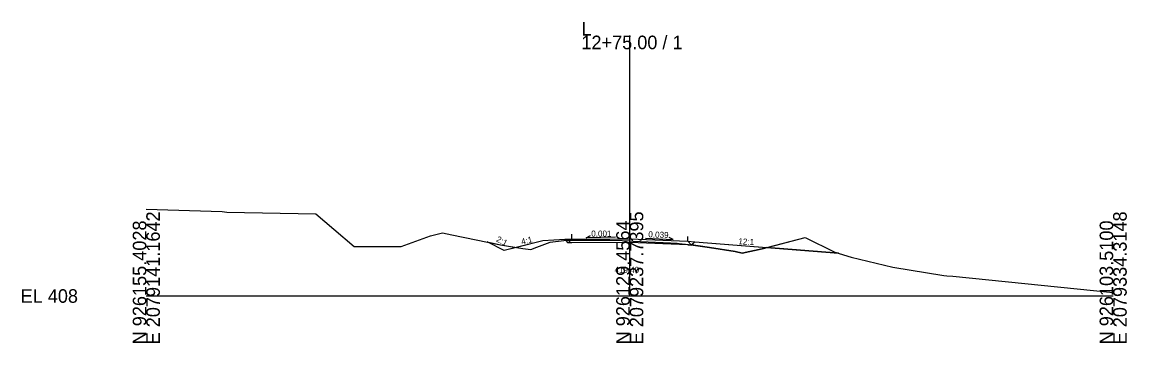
# Model space of a CAD drawing. Extents: x -26 to 10503, y -10 to 9546.
# Drawn here: x -25.7 to 202.8, y 5490.3 to 5556.6 of the extents above; entities that cross this region are included whole.
import ezdxf

# ---------------------------------------------------------------- set-up
doc = ezdxf.new("R2010")
doc.units = 0
for name, color, linetype in [('Default', 7, 'Continuous'), ('Exist XS Center Line Elevation Label', 7, 'Continuous'), ('Exist XS Ground Line', 7, 'Continuous'), ('Old_Level_63', 7, 'Continuous'), ('Prop XS Ditch Slope Text', 7, 'Continuous'), ('Prop XS Dump Level', 7, 'Continuous'), ('Prop XS EOT Tick Mark', 7, 'Continuous'), ('Prop XS Finish Grade', 7, 'Continuous'), ('Prop XS Finish Grade Earthwork', 7, 'Continuous'), ('Prop XS Finish Grade Pavement', 7, 'Continuous'), ('Prop XS Pvmt Edge Slope', 7, 'Continuous'), ('Prop XS SE Text', 7, 'Continuous'), ('Prop XS Side Slope Text', 7, 'Continuous'), ('Prop XS Subgrade Earthwork', 7, 'Continuous')]:
    doc.layers.add(name, color=color, linetype=linetype)

msp = doc.modelspace()

# ---------------------------------------------------------------- linework, layer by layer
at = {"layer": 'Default'}
for points in [[(74, 5509.4), (70.48, 5511.16), (73.27, 5510.6), (76.56, 5510.05)], [(86.58, 5511.68), (82, 5511.4), (76.56, 5510.05), (77.9, 5509.82), (79.52, 5509.6), (80.76, 5510.06), (83.55, 5511.13), (86.34, 5511.47), (86.75, 5511.52)], [(88, 5511.02), (87.25, 5511.02), (86.75, 5511.52), (87.14, 5511.56), (95.88, 5511.53), (98.43, 5511.5), (100, 5511.4), (100.73, 5511.36), (108.4, 5510.98), (109.84, 5510.89), (110.25, 5510.86), (112.18, 5510.63), (112.79, 5510.55), (112.78, 5510.53), (112, 5510.56), (100, 5511.03)], [(113.45, 5511.2), (128.39, 5510), (127.38, 5509.74), (123.27, 5508.84), (121.81, 5509.18), (116.49, 5510.05), (112.79, 5510.55)], [(128.39, 5510), (136.32, 5512.06), (142.4, 5509.07), (143.2, 5508.82)]]:
    msp.add_lwpolyline(points, close=True, dxfattribs=at)
at = {"layer": 'Exist XS Ground Line'}
for p, q in [((0, 5517.94), (15.72, 5517.49)), ((15.72, 5517.49), (16.67, 5517.35)), ((16.67, 5517.35), (35.07, 5516.99)), ((35.07, 5516.99), (38.81, 5513.81)), ((38.81, 5513.81), (43.02, 5510.24)), ((52.71, 5510.23), (58.78, 5512.41)), ((58.78, 5512.41), (61.27, 5513.07)), ((61.27, 5513.07), (63.19, 5512.64)), ((63.19, 5512.64), (73.27, 5510.6)), ((43.02, 5510.24), (46.28, 5510.26)), ((46.28, 5510.26), (52.71, 5510.23)), ((73.27, 5510.6), (77.9, 5509.82)), ((79.52, 5509.6), (80.76, 5510.06)), ((80.76, 5510.06), (83.55, 5511.13)), ((83.55, 5511.13), (86.34, 5511.47)), ((86.34, 5511.47), (87.14, 5511.56)), ((87.14, 5511.56), (95.88, 5511.53)), ((95.88, 5511.53), (98.43, 5511.5)), ((98.43, 5511.5), (100, 5511.4)), ((100, 5511.4), (100.73, 5511.36)), ((100.73, 5511.36), (108.4, 5510.98)), ((108.4, 5510.98), (109.84, 5510.89)), ((109.84, 5510.89), (110.25, 5510.86)), ((110.25, 5510.86), (112.18, 5510.63)), ((112.18, 5510.63), (116.49, 5510.05)), ((116.49, 5510.05), (121.81, 5509.18)), ((127.38, 5509.74), (136.32, 5512.06)), ((136.32, 5512.06), (142.4, 5509.07)), ((77.9, 5509.82), (79.52, 5509.6)), ((121.81, 5509.18), (123.27, 5508.84)), ((123.27, 5508.84), (127.38, 5509.74)), ((142.4, 5509.07), (145.78, 5508.01)), ((145.78, 5508.01), (154.42, 5505.95)), ((154.42, 5505.95), (164.99, 5504.22)), ((164.99, 5504.22), (165.59, 5504.18)), ((165.59, 5504.18), (166.84, 5504.12)), ((166.84, 5504.12), (200, 5500.69))]:
    msp.add_line(p, q, dxfattribs=at)
at = {"layer": 'Old_Level_63'}
for p, q in [((100, 5500), (100, 5553.81)), ((0, 5500), (100, 5500)), ((100, 5500), (200, 5500))]:
    msp.add_line(p, q, dxfattribs=at)
at = {"layer": 'Prop XS EOT Tick Mark'}
for p, q in [((88, 5511.77), (88, 5512.77)), ((112, 5511.31), (112, 5512.31))]:
    msp.add_line(p, q, dxfattribs=at)
at = {"layer": 'Prop XS Finish Grade'}
for p, q in [((88, 5511.77), (86.58, 5511.68)), ((112, 5511.31), (113.45, 5511.2))]:
    msp.add_line(p, q, dxfattribs=at)
at = {"layer": 'Prop XS Finish Grade Earthwork'}
for p, q in [((74, 5509.4), (70.48, 5511.16)), ((82, 5511.4), (74, 5509.4)), ((86.58, 5511.68), (82, 5511.4)), ((113.45, 5511.2), (143.2, 5508.82))]:
    msp.add_line(p, q, dxfattribs=at)
at = {"layer": 'Prop XS Finish Grade Pavement'}
for p, q in [((88, 5511.77), (100, 5511.78)), ((100, 5511.78), (112, 5511.31))]:
    msp.add_line(p, q, dxfattribs=at)
at = {"layer": 'Prop XS Pvmt Edge Slope'}
for p, q in [((88, 5511.77), (87.25, 5511.02)), ((112, 5511.31), (112.78, 5510.53))]:
    msp.add_line(p, q, dxfattribs=at)
at = {"layer": 'Prop XS SE Text'}
for points in [[(97.03, 5512.15), (91.01, 5512.04), (91.87, 5512.5)], [(103.23, 5511.92), (108.98, 5511.65), (108.13, 5512.11)]]:
    msp.add_lwpolyline(points, dxfattribs=at)
at = {"layer": 'Prop XS Subgrade Earthwork'}
for p, q in [((87.25, 5511.02), (86.58, 5511.68)), ((88, 5511.02), (87.25, 5511.02)), ((100, 5511.03), (88, 5511.02)), ((112, 5510.56), (100, 5511.03)), ((112, 5510.56), (112.78, 5510.53)), ((112.78, 5510.53), (113.45, 5511.2))]:
    msp.add_line(p, q, dxfattribs=at)

# ---------------------------------------------------------------- texts
at = {"layer": 'Exist XS Center Line Elevation Label'}
msp.add_text('419.40', height=1.25, rotation=360, dxfattribs=at).set_placement((96.84, 5504.78))
at = {"layer": 'Old_Level_63'}
for s, p in [('L', (90, 5553.81)), ('12+75.00 / 1', (90, 5551.01)), ('EL 408', (-26, 5498.6))]:
    msp.add_text(s, height=2.8, dxfattribs=at).set_placement(p)
for s, p in [('E 2079141.1642', (2.8, 5490)), ('E 2079237.7395', (102.8, 5490)), ('E 2079334.3148', (202.8, 5490)), ('N 926155.4028', (0, 5490)), ('N 926129.4564', (100, 5490)), ('N 926103.5100', (200, 5490))]:
    msp.add_text(s, height=2.8, rotation=90, dxfattribs=at).set_placement(p)
at = {"layer": 'Prop XS Ditch Slope Text'}
for s, rotation, p in [('4:1', 14.0362, (77.71, 5510.57)), ('12:1', 356.5563, (122.45, 5510.7))]:
    msp.add_text(s, height=1.25, rotation=rotation, dxfattribs=at).set_placement(p)
at = {"layer": 'Prop XS Dump Level'}
msp.add_text('Case1', height=0.04, dxfattribs=at).set_placement((120, 5510.63))
at = {"layer": 'Prop XS SE Text'}
for s, rotation, p in [('0.001', 0.0573, (92.04, 5512.27)), ('0.039', 357.7666, (103.83, 5512.13))]:
    msp.add_text(s, height=1.25, rotation=rotation, dxfattribs=at).set_placement(p)
at = {"layer": 'Prop XS Side Slope Text'}
msp.add_text('2:1', height=1.25, rotation=333.4349, dxfattribs=at).set_placement((72.26, 5511.33))

doc.saveas('drawing.dxf')
